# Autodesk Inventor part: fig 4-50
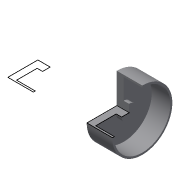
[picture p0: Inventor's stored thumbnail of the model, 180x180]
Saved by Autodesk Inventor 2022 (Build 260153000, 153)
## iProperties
Created: 2004-05
Part Number: fig 4-50
Document SubType Name: Modeling
Designer: CADCIM Technologies
Manufacturer: Standard
Standards Organization: Custom
Density: 1 g/cm^3
Material: Generic
Appearance: Default
Author: CADCIM Technologies
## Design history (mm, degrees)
sketch "Sketch1"
  geometry: L1 (30.083, 49.92)-(16.646, 49.92); L2 (16.646, 49.92)-(16.646, 17.104); L3 (16.646, 17.104)-(44.553, 17.104); L4 (44.553, 17.104)-(44.553, 19.171); L5 (44.553, 19.171)-(24.139, 19.171); L6 (24.139, 19.171)-(24.139, 41.652); L7 (24.139, 41.652)-(30.083, 41.652); L8 (30.083, 41.652)-(30.083, 49.92); L9 (116.437, 49.92)-(103, 49.92); L10 (103, 49.92)-(103, 17.104); L11 (103, 17.104)-(130.907, 17.104); L12 (130.907, 17.104)-(130.907, 19.171); L13 (130.907, 19.171)-(110.494, 19.171); L14 (110.494, 19.171)-(110.494, 41.652); L15 (110.494, 41.652)-(116.437, 41.652); L16 (116.437, 41.652)-(116.437, 49.92)
  constraints: 32 end point, 2 horizontal
revolve "Revolution1" sketch "Sketch1" stored, may be unused: angle "d0" = 270 deg
body "Solid1"
